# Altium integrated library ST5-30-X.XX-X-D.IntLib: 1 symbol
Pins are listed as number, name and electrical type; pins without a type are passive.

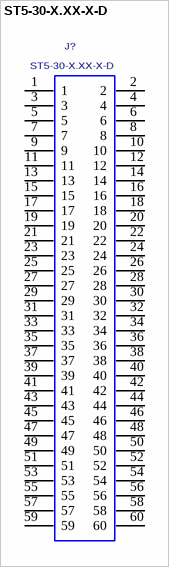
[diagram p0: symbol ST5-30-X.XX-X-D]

## ST5-30-X.XX-X-D
designator J?
0.5 MM TERMINAL STRIP ASSEMBLY, 60 PINS.; MANUFACTURER: SAMTEC
footprint ST5-30-X.XX-X-D
pins: 1, 2, 3, 4, 5, 6, 7, 8, 9, 10, 11, 12, 13, 14, 15, 16, 17, 18, 19, 20, 21, 22, 23, 24, 25, 26, 27, 28, 29, 30, 31, 32, 33, 34, 35, 36, 37, 38, 39, 40, 41, 42, 43, 44, 45, 46, 47, 48, 49, 50, 51, 52, 53, 54, 55, 56, 57, 58, 59, 60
